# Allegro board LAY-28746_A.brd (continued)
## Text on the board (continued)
DISPLAY_TOP: A -TARGET:10 MILS+/-10% | B -TARGET: 38 MILS+/-10% | C -TARGET:10 MILS+/-10% | 16. BASIC GRID INCREMENT AT 1:1 IS .0001. | 17. SUPPLIER MARKINGS - ON SOLDER SIDE ONLY, WHERE SHOWN. | 1. THIS DRAWING SPECIFIES THE REQUIREMENTS FOR A | 2. THE PWB MUST BE LEAD FREE ASSEMBLY PROCESS COMPATIBLE AND MUST BE ABLE TO HANDLE | 3. BASE MATERIAL - LAMINATE AND PREPREG SHALL MEET IPC-4101B-26, 83 or 98 | 4. COPPER FOIL WEIGHT - SEE STACKUP DETAIL 'A' | 5. CHARACTERISTIC IMPEDANCE - SEE DETAIL "B" AND "C". | 6. MINIMUM CONDUCTIVE WIDTH/SPACING TO BE .003"/.0035" | 7. PLATING FINISH - BOTH SIDES ENIG (ELECTROLESS NICKEL IMMERSION GOLD): | 8. ALL THROUGH HOLE VIAS MAY BE PLATED SHUT. | 9. SOLDERMASK - GREEN COLOR BOTH SIDES. | 10. SILKSCREEN - WHITE EPOXY INK, BOTH SIDES.  NO SILK ON PADS. | 11. ELECTRICAL TEST - 100% IPC-D-356. | 12. PRINTED WIRING BOARD IS TO BE INDIVIDUALLY BAGGED. | 13. DRC'S MUST BE RUN ON THE GERBER BEFORE BUILDING BOARDS, | UNLESS PRIOR APPROVAL IS GIVEN IN WRITING BY FREESCALE. | 14. TEARDROPS MAYBE ADDED AT THE FAB HOUSE TO ALL SIGNAL LAYERS. | 15. 2 SOLDER SAMPLES TO BE PROVIDED. | 18. THE PWB WILL BE MARKED AS LEAD FREE BY USE OF AN INK STAMP Pb | 19. THE PWB WILL BE MARKED AS LEAD FREE PROCESS COMPATIBLE BY USE OF AN INK STAMP 260 C | 21. FINISHED PCB MUST BE PANELIZED FOR ASSEMBLY ACCORDING TO CONTRACT MANUFACTURERS REQUIREMENTS. | 22. INTENTIONAL SHORTS AT: | MODIFICATION OF SOLDERMASK IS NOT ALLOWED WITHOUT WRITTEN PERMISSION FROM FREESCALE. | WITH SPECIFICATION IPC-A-600 CLASS 2 (LATEST REVISION). | 23. OVERALL PCB DIELECTRIC THICKNESS ARE TARGETED (A) 10 MILS+/-10%, B) 38 MILS +/-10% AND (C) 10 MILS +/-  10%. | A MINIMUM OF 5 CYCLES AT 260 DEGREES CELSIUS FOR 10 SECONDS. | THE ADDITION OF RAILS AND .125' NON-PLATED TOOLING HOLES ARE AT THE DISCRETION OF | CONTRACT MANUFACTURER. PANELIZATION MUST BE APPROVED BY CONTRACT MANUFACTURER. | SH19 Vcc & P3V3_K22F | SH40 PTC3 & DIO0 | SH41 PTC4 & DIO1 | SH44 N23913269 & RESET_B_XCVR | SH45 PTA18 & DIO5/CLKOUT | SH46 PTA19 & DIO4 | SH47 SWD_CLK & PTA0/SWD_CLK | AS SHOWN IN DETAIL 'A'. ADJUSTMENT IN SUBSTRATE B IS ALLOWED TO MEET OVERALL HEIGHT REQUIREMENT. | 2.540-6.350 MICRON (100-250 MICROINCH) OF NICKEL. | .05080-.232 MICRON (2-8 MICROINCH) OF GOLD OVER | Tg - MUST BE GREATER THAN OR EQUAL TO 150 DEGREES CELSIUS. | Td - MUST BE GREATER THAN OR EQUAL TO 330 DEGREES CELSIUS. | Er - MUST BE FROM 4.2 TO 4.4 | - MUST BE UL RECOGNIZED AND MUST HAVE AN ID THAT CONFORMS TO UL94V-0 | PRINTED WIRING BOARD IN ACCORDANCE | 5 | 16 | 17 | 8 | 23 | 20. ALL PLATED AND NON-PLATED THROUGH HOLES ARE TO BE DRILLED AT PRIMARY DRILL STEP. | ALL HOLE LOCATION TOLERANCES ARE TO BE +/-.002 IN REFERENCE TO THE PRIMARY DATUM. | IMPEDANCE 90 OHMS | IMPEDANCE 50 OHMS | PRIMARY SIDE VIEW | 0.062"+/-10% | DETAIL C | DIFFERENTIAL PAIR | IMPEDANCE REQUIREMENTS | SINGLE ENDED | DETAIL B
User.8: 03/13/15 | 06/29/15 | A | PRODUCTION RELEASE
User.9: FIGURE | SIZE | 8.0 | 31.0 | 63.0 | 43.0 | 93.0 | 98.425x39.37 | DRILL CHART: TOP to BOTTOM | ALL UNITS ARE IN MILS | TOLERANCE | +0.0/-8.0 | +2.0/-2.0 | +3.0/-3.0 | PLATED | NON-PLATED | QTY | 248 | 20 | 2 | 4
User.12: L1 | L4 | LAYERS | Trace Width | (Mils) | 18 | SINGLE ENDED | Impedance | (Ohms) | 50 | 11.5 | DIFFERENTIAL | Trace Spacing | "Airgap" | 5.50 | 90
